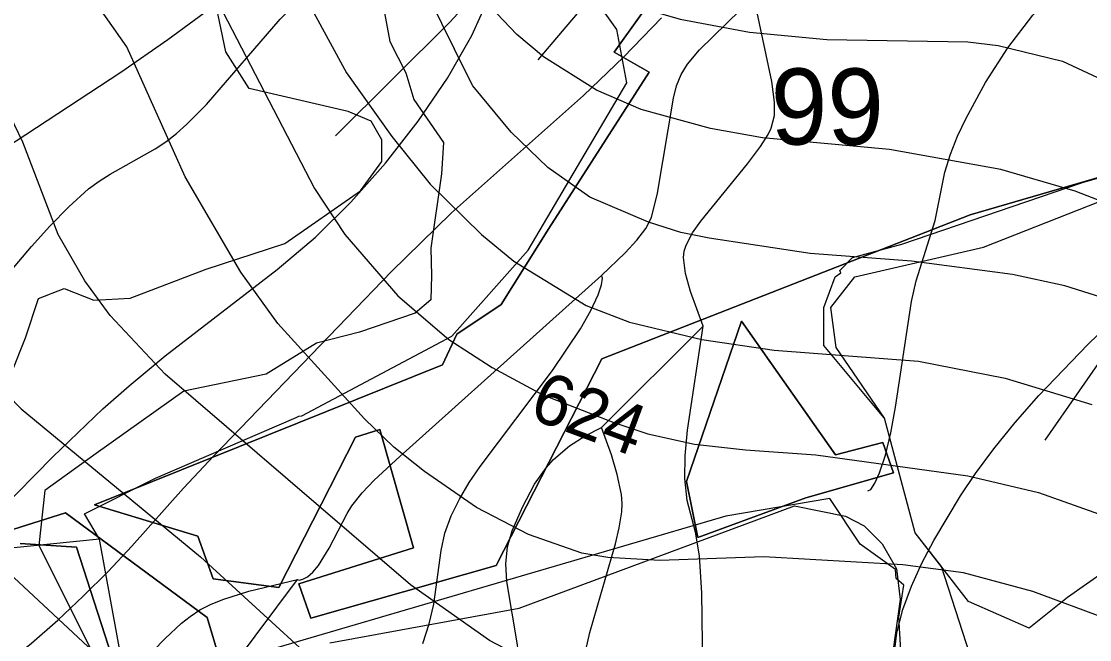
# Model space of a CAD drawing. Extents: x -709584 to -702006, y -1161789 to -1157496.
# Drawn here: x -706146.4 to -705935.7, y -1160043.8 to -1159921.9 of the extents above; entities that cross this region are included whole.
import ezdxf

# ---------------------------------------------------------------- set-up
doc = ezdxf.new("R2010")
doc.units = 0
for name, color, linetype in [('102_obvod PÚ', 7, 'Continuous'), ('120_vrstevnice hlavní', 7, 'Continuous'), ('121_vrstevnice hlavní_popis', 7, 'Continuous'), ('122_vrstevnice základní', 7, 'Continuous'), ('408_BPEJ_linie', 7, 'Continuous'), ('409_BPEJ_popis', 7, 'Continuous'), ('411_akumulovaný odtok', 7, 'Continuous'), ('419_LPIS PB', 7, 'Continuous')]:
    doc.layers.add(name, color=color, linetype=linetype)

msp = doc.modelspace()

# ---------------------------------------------------------------- linework, layer by layer
at = {"layer": '102_obvod PÚ'}
for points in [[(-706132.01, -1160017.23), (-706063.34, -1159989.61), (-706060.53, -1159983.56), (-706051.79, -1159977.72), (-706042.41, -1159962.75), (-706022.6, -1159931.91), (-706029.49, -1159927.99), (-706024.08, -1159920.31), (-706017.53, -1159909.69), (-706010.59, -1159892.53), (-706005.92, -1159884.25), (-705993.15, -1159870.34), (-705985.19, -1159860.82), (-705963.63, -1159831.62), (-705937.51, -1159839.54), (-705930.71, -1159851.23)], [(-705930.71, -1159851.23), (-705937.51, -1159839.54), (-705963.63, -1159831.62), (-705985.19, -1159860.82), (-705993.15, -1159870.34), (-706005.92, -1159884.25), (-706010.59, -1159892.53), (-706017.53, -1159909.69), (-706024.08, -1159920.31), (-706029.49, -1159927.99), (-706022.6, -1159931.91), (-706042.41, -1159962.75), (-706051.79, -1159977.72), (-706060.53, -1159983.56), (-706063.34, -1159989.61), (-706132.01, -1160017.23)], [(-705880.49, -1159937.13), (-705959.3, -1159960.06), (-706031.94, -1159988.44), (-706052.79, -1160029.25), (-706089.31, -1160039.58), (-706091.72, -1160032.86), (-706069.11, -1160025.74), (-706075.72, -1160002.39), (-706080.5, -1160003.91), (-706095.63, -1160033.58), (-706108.58, -1160031.88), (-706111.63, -1160023.46), (-706132.01, -1160017.23)], [(-706132.01, -1160017.23), (-706111.63, -1160023.46), (-706108.58, -1160031.88), (-706095.63, -1160033.58), (-706080.5, -1160003.91), (-706075.72, -1160002.39), (-706069.11, -1160025.74), (-706091.72, -1160032.86), (-706089.31, -1160039.58), (-706052.79, -1160029.25), (-706031.94, -1159988.44), (-705959.3, -1159960.06), (-705880.49, -1159937.13)], [(-706015.27, -1160012.66), (-706004.41, -1159981.02), (-705985.87, -1160007.42), (-705976.51, -1160004.98), (-705974.45, -1160010.97), (-705991.68, -1160015.84), (-706013.02, -1160023.71), (-706015.27, -1160012.66)], [(-706015.27, -1160012.66), (-706013.02, -1160023.71), (-705991.68, -1160015.84), (-705974.45, -1160010.97), (-705976.51, -1160004.98), (-705985.87, -1160007.42), (-706004.41, -1159981.02), (-706015.27, -1160012.66)], [(-706190.18, -1160035.39), (-706137.74, -1160018.82), (-706109.77, -1160039.47), (-706107.33, -1160047.61), (-706126.51, -1160053.66), (-706135.55, -1160025.58), (-706146.66, -1160024.88)], [(-706146.66, -1160024.88), (-706135.55, -1160025.58), (-706126.51, -1160053.66), (-706107.33, -1160047.61), (-706109.77, -1160039.47), (-706137.74, -1160018.82), (-706190.18, -1160035.39)]]:
    msp.add_lwpolyline(points, dxfattribs=at)
at = {"layer": '120_vrstevnice hlavní'}
for points in [[(-706204.73, -1159905.53), (-706198.04, -1159923.77), (-706187.35, -1159946.56), (-706174.67, -1159965.94), (-706157, -1159987.6), (-706146.46, -1159998.29), (-706111.12, -1160027.5), (-706077.49, -1160058.28), (-706072.79, -1160061.84), (-706062.1, -1160068.54), (-706056.26, -1160071.53), (-706050.7, -1160073.88), (-706043.59, -1160076.13), (-706037.31, -1160077.23), (-706030.32, -1160077.38), (-706012.92, -1160072.49), (-705983.77, -1160064.61), (-705952.64, -1160058.71), (-705937.48, -1160056.82)], [(-706066.05, -1159917.09), (-706061.1, -1159927.33)], [(-705852.98, -1160024.04), (-705865.58, -1160016.55), (-705883.13, -1160006.13), (-705903.79, -1159991.45), (-705917.61, -1159982.9), (-705931, -1159977.06), (-705940.62, -1159974.07), (-705950.95, -1159971.79), (-705970.9, -1159969.22), (-705990.85, -1159967.65), (-706010.8, -1159964.66), (-706016.38, -1159963.53), (-706022.77, -1159961.53), (-706034.31, -1159956.54), (-706042.58, -1159950.7), (-706049.84, -1159943.72), (-706057.4, -1159934.6), (-706061.1, -1159927.33)]]:
    msp.add_lwpolyline(points, dxfattribs=at)
at = {"layer": '122_vrstevnice základní'}
for points in [[(-706294.51, -1159822.03), (-706250.48, -1159859.93), (-706244.78, -1159865.49), (-706240.07, -1159871.9), (-706234.94, -1159883.3), (-706227.25, -1159920.35), (-706221.98, -1159937.45), (-706218.7, -1159946), (-706214.57, -1159954.54), (-706206.59, -1159968.79), (-706200.75, -1159977.34), (-706188.96, -1159992.37), (-706182.93, -1159999), (-706109.98, -1160066.97), (-706091.17, -1160085.5), (-706081.56, -1160089.38), (-706061.47, -1160090.96), (-706042.29, -1160091.2)], [(-706041.01, -1159861.21), (-706046.09, -1159868.77), (-706052.66, -1159875.6), (-706056.54, -1159881.16), (-706057.11, -1159885.58), (-706056.97, -1159890.71), (-706055.54, -1159895.84), (-706053.26, -1159900.97), (-706046.99, -1159907.81), (-706041.86, -1159911.51), (-706035.31, -1159914.93), (-706023.34, -1159919.49), (-706016.5, -1159921.49), (-706002.82, -1159924.05), (-705987.57, -1159925.48), (-705959.79, -1159925.9), (-705953.8, -1159926.62), (-705941.12, -1159929.75), (-705928.3, -1159935.74)], [(-705951.3, -1160051.51), (-705957.33, -1160049.33), (-705965.77, -1160047.88), (-705972.24, -1160047.04), (-705979.74, -1160046.88), (-705987.74, -1160047.04), (-705995.7, -1160048.02), (-706013.65, -1160052.3), (-706018.39, -1160053.19), (-706023.62, -1160053.44), (-706031.6, -1160052.87), (-706041.58, -1160050.16), (-706046.69, -1160047.92), (-706054.12, -1160044.03), (-706069.65, -1160033.06), (-706118.1, -1159991.45), (-706128.93, -1159979.91), (-706133.92, -1159973.07), (-706139.19, -1159963.95), (-706146.17, -1159945.71), (-706149.45, -1159938.87), (-706159.57, -1159925.19), (-706172.96, -1159910.23)], [(-705932.43, -1160039.76), (-705946.96, -1160034.34), (-705960.64, -1160030.64), (-705972.61, -1160029.07), (-705999.97, -1160027.5), (-706020.49, -1160028.21), (-706030.75, -1160027.64), (-706035.88, -1160026.79), (-706046.42, -1160023.08), (-706056.68, -1160017.81), (-706066.94, -1160010.69), (-706073, -1160005.91), (-706078.77, -1160000.28), (-706095.87, -1159981.48), (-706103.14, -1159971.36), (-706114.11, -1159952.55), (-706125.65, -1159926.9), (-706132.78, -1159916.64)], [(-705836.19, -1160013.74), (-705859.76, -1159996.01), (-705875.72, -1159985.75), (-705899.94, -1159972.36), (-705924.16, -1159960.96), (-705938.56, -1159955.4), (-705953.23, -1159951.12), (-705975.18, -1159947.14), (-706000.26, -1159944.86), (-706010.52, -1159943), (-706024.2, -1159939.3), (-706033.03, -1159935.45), (-706043.43, -1159928.9), (-706048.7, -1159924.48), (-706056.54, -1159916.21)], [(-706107.55, -1159918.35), (-706088.6, -1159954.83), (-706082.62, -1159963.95), (-706072.21, -1159976.06), (-706062.1, -1159984.61), (-706053.55, -1159990.17), (-706043.57, -1159995.58), (-706029.61, -1160001), (-706022.85, -1160003.28), (-706013.65, -1160005.27), (-706003.58, -1160006.41), (-705989.71, -1160007.41), (-705959.79, -1160011.54), (-705945.82, -1160014.82), (-705927.87, -1160021.23)], [(-706089.17, -1159919.49), (-706082.33, -1159932.03), (-706073.35, -1159944.57), (-706065.8, -1159953.98), (-706055.69, -1159963.95), (-706049.27, -1159969.22), (-706035.03, -1159977.91), (-706026.48, -1159981.19), (-706012.23, -1159984.61), (-705997.98, -1159986.75), (-705969.48, -1159988.89), (-705952.38, -1159992.3), (-705935.28, -1159997.44)]]:
    msp.add_lwpolyline(points, dxfattribs=at)
at = {"layer": '408_BPEJ_linie'}
for points in [[(-706131, -1160024), (-706134, -1160019), (-706120, -1160012), (-706092.24, -1160000), (-706091.72, -1159999.78), (-706091.13, -1159999.73), (-706061.5, -1159984), (-706046.5, -1159967), (-706027, -1159934), (-706029, -1159923.5), (-706049, -1159895.5), (-706058.5, -1159874.5), (-706051.5, -1159868), (-706033.5, -1159863), (-706024, -1159886.5), (-706011.5, -1159889.5), (-705997, -1159877), (-705967.43, -1159835.34), (-705965.3, -1159834.4), (-705962.63, -1159831.21)], [(-705958, -1160051), (-705964.98, -1160029.43), (-705970.16, -1160022.75), (-705976.17, -1160000.15), (-705976.3, -1160000), (-705988.18, -1159985.84), (-705988.18, -1159978.31), (-705985.93, -1159972.28), (-705984.82, -1159971.49), (-705985, -1159971), (-705982.5, -1159968.5), (-705972.8, -1159965.83), (-705937.13, -1159953.68), (-705884.58, -1159938.61), (-705879.05, -1159936.81), (-705879.5, -1159931), (-705888, -1159919), (-705935, -1159863.5), (-705936, -1159850), (-705940, -1159843), (-705962.63, -1159831.21)], [(-705958, -1160051), (-705972.5, -1160053.5), (-705973.4, -1160039.44), (-705972.4, -1160033.1), (-705973.89, -1160031.78), (-705974, -1160030), (-705981, -1160025), (-705987, -1160016), (-706007.5, -1160019.5), (-706108.4, -1160049.1), (-706121.95, -1160050.59), (-706125.16, -1160049.51), (-706126.42, -1160049.2), (-706131, -1160024)], [(-706131, -1160024), (-706150.5, -1160026), (-706193, -1160042), (-706290.5, -1160101), (-706319.5, -1160119.5), (-706347, -1160131), (-706404.5, -1160146), (-706459, -1160146), (-706481.5, -1160149.5), (-706501, -1160161.5), (-706523.5, -1160182), (-706546, -1160220), (-706564.5, -1160251.5), (-706640, -1160329)]]:
    msp.add_lwpolyline(points, dxfattribs=at)
at = {"layer": '411_akumulovaný odtok'}
for p, q in [((-705944.49, -1160004.5), (-705921.99, -1159972)), ((-706031.99, -1160002), (-706011.99, -1159982)), ((-706106.99, -1160052), (-706091.99, -1160032))]:
    msp.add_line(p, q, dxfattribs=at)
for points in [[(-706044.49, -1159929.5), (-706024.2, -1159905.45), (-706016.79, -1159897.19), (-706008.45, -1159889.47), (-705976.99, -1159862)], [(-706161.99, -1159987), (-706144.45, -1159966.3), (-706140.82, -1159962.28), (-706137.1, -1159958.45), (-706133.16, -1159954.94), (-706131.06, -1159953.38), (-706128.92, -1159952.01), (-706120.04, -1159947.04), (-706117.93, -1159945.64), (-706115.81, -1159943.99), (-706113.79, -1159942.19), (-706109.95, -1159938.29), (-706095.39, -1159921.49), (-706089.62, -1159915.47), (-706081.12, -1159907.87), (-706061.99, -1159892)], [(-706284.73, -1160082.36), (-706273.96, -1160068.38), (-706268.75, -1160062.01), (-706246.59, -1160037.13), (-706241.22, -1160030.79), (-706236.12, -1160024.29), (-706224.77, -1160008.22), (-706220.15, -1160002.16), (-706215.29, -1159996.34), (-706210.16, -1159990.79), (-706204.74, -1159985.61), (-706199.69, -1159981.4), (-706194.08, -1159977.32), (-706166.25, -1159957.75), (-706126.83, -1159931.94), (-706117.57, -1159925.5), (-706086.36, -1159902.54), (-706081.34, -1159899.16), (-706078.22, -1159897.38), (-706076.99, -1159897)], [(-706084.49, -1159944.5), (-706061.92, -1159922.04), (-706059.53, -1159919.48), (-706058.12, -1159917.67), (-706056.99, -1159915.73), (-706055.82, -1159912.59), (-706054.63, -1159908.18), (-706051.99, -1159897)], [(-705979.49, -1160014.5), (-705978.92, -1160014.2), (-705978.1, -1160012.99), (-705977.15, -1160010.96), (-705976, -1160007.45), (-705974.96, -1160003.05), (-705974.03, -1159998.01), (-705970.85, -1159977.12), (-705969.93, -1159973.07), (-705966.21, -1159961.17), (-705964.3, -1159951.66), (-705963.2, -1159948.09), (-705961.78, -1159944.52), (-705960.11, -1159940.97), (-705956.26, -1159933.93), (-705951.85, -1159927.1), (-705946.91, -1159920.64), (-705944.25, -1159917.6), (-705941.46, -1159914.75), (-705938.5, -1159912.13), (-705935.33, -1159909.82)], [(-706150.89, -1160018.59), (-706140.23, -1160007.8), (-706130.34, -1159998.33), (-706125.18, -1159993.77), (-706118.05, -1159987.89), (-706095.99, -1159970.83), (-706088.45, -1159964.45), (-706081.46, -1159957.55), (-706074.59, -1159949.83), (-706068.14, -1159941.58), (-706062.38, -1159933.1), (-706057.58, -1159924.68), (-706053.78, -1159916.2)], [(-706031.99, -1159972), (-706027.35, -1159967.54), (-706025.05, -1159965.08), (-706023.25, -1159962.74), (-706022.18, -1159960.55), (-706020.94, -1159955.76), (-706017.81, -1159937.01), (-706017.19, -1159934.61), (-706016.32, -1159932.35), (-706015.06, -1159930.32), (-706012.71, -1159927.53), (-706001.99, -1159917)], [(-706011.99, -1159982), (-706014.47, -1159975.17), (-706015.46, -1159971.6), (-706015.84, -1159968.5), (-706015.69, -1159967.24), (-706015.31, -1159966.01), (-706014.06, -1159963.63), (-706012.45, -1159961.33), (-706003.24, -1159949.99), (-706000.63, -1159946.55), (-705999.15, -1159944.2), (-705998.56, -1159942.98), (-705997.9, -1159940.46), (-705997.86, -1159937.83), (-705998.39, -1159933.74), (-706001.99, -1159917)], [(-706161.41, -1160058.28), (-706144.42, -1160044.53), (-706139.24, -1160039.97), (-706134.21, -1160035.25), (-706129.33, -1160030.39), (-706124.63, -1160025.39), (-706114.46, -1160013.96), (-706108.47, -1160007.57), (-706073.52, -1159971.29), (-706061.61, -1159959.66), (-706035.54, -1159936.52), (-706027.66, -1159928.93), (-706020.16, -1159921.22)], [(-706091.99, -1160032), (-706091.61, -1160032.1), (-706090.9, -1160031.93), (-706089.98, -1160031.43), (-706088.92, -1160030.51), (-706087.83, -1160029.2), (-706085.7, -1160025.82), (-706082.17, -1160018.93), (-706081.28, -1160017.48), (-706079.2, -1160014.86), (-706076.84, -1160012.41), (-706071.81, -1160007.73), (-706031.99, -1159972)], [(-706067.23, -1160044.61), (-706066.02, -1160040.73), (-706065.1, -1160036.84), (-706063.63, -1160026.25), (-706062.88, -1160022.84), (-706061.66, -1160019.42), (-706060.03, -1160016.11), (-706058.1, -1160012.86), (-706055.94, -1160009.67), (-706041.68, -1159990.73), (-706036.18, -1159982.52), (-706034.12, -1159978.9), (-706032.69, -1159975.84), (-706032.03, -1159973.88), (-706031.81, -1159972.56), (-706031.99, -1159972)], [(-705974.31, -1160046.93), (-705973.74, -1160042.48), (-705972.55, -1160037.87), (-705970.88, -1160033.31), (-705968.83, -1160028.79), (-705966.49, -1160024.31), (-705961.21, -1160015.47), (-705958.25, -1160011.06), (-705954.64, -1160006.19), (-705950.43, -1160001.02), (-705945.75, -1159995.72), (-705936.07, -1159985.65), (-705921.99, -1159972)], [(-705996.99, -1160097), (-705997.63, -1160095.69), (-705998.51, -1160092.47), (-705998.86, -1160090.4), (-705999.6, -1160083.1), (-706000.27, -1160080.54), (-706001.23, -1160078.17), (-706002.33, -1160076.09), (-706007.35, -1160067.99), (-706009.56, -1160063.74), (-706010.41, -1160061.52), (-706011.02, -1160059.22), (-706011.43, -1160056.85), (-706012, -1160049.52), (-706012.25, -1160034.59), (-706012.7, -1160027.29), (-706013.47, -1160022.64), (-706015.13, -1160016.39), (-706015.58, -1160012.07), (-706015.5, -1160007.58), (-706015.02, -1160002.5), (-706011.99, -1159982)], [(-706051.99, -1160082), (-706052.88, -1160081.15), (-706053.5, -1160080.11), (-706054.04, -1160078.73), (-706054.36, -1160077.03), (-706054.41, -1160075.1), (-706054.24, -1160073.05), (-706053.36, -1160068.93), (-706049.13, -1160057), (-706048.32, -1160053.61), (-706048.06, -1160050.15), (-706048.57, -1160044.84), (-706050.7, -1160032.37), (-706050.91, -1160028.86), (-706050.54, -1160025.52), (-706049.6, -1160022.36), (-706047.62, -1160017.71), (-706045.24, -1160013.18), (-706042.94, -1160009.95), (-706041.49, -1160008.33), (-706038.32, -1160005.59), (-706035.26, -1160003.63), (-706031.99, -1160002)], [(-706036.99, -1160082), (-706035.12, -1160076.6), (-706034.02, -1160072.72), (-706033.29, -1160068.82), (-706033.19, -1160067.06), (-706033.55, -1160064.01), (-706035.35, -1160056.5), (-706035.86, -1160053.49), (-706035.96, -1160051.98), (-706035.73, -1160048.82), (-706034.32, -1160042.46), (-706029.27, -1160024.96), (-706028.51, -1160021.78), (-706028, -1160018.61), (-706027.93, -1160016.98), (-706028.09, -1160015.21), (-706028.9, -1160011.29), (-706030.07, -1160007.41), (-706031.99, -1160002)], [(-706174.49, -1160104.5), (-706122.71, -1160048.44), (-706118.07, -1160043.62), (-706114.85, -1160040.62), (-706113.16, -1160039.25), (-706111.24, -1160037.98), (-706109.11, -1160036.91), (-706106.71, -1160035.94), (-706101.6, -1160034.31), (-706091.99, -1160032)]]:
    msp.add_lwpolyline(points, dxfattribs=at)
at = {"layer": '419_LPIS PB'}
for points in [[(-706077.44, -1159906.03), (-706073.74, -1159925.86), (-706070.59, -1159932.02), (-706069.01, -1159937.32), (-706063.2, -1159945.79), (-706063.55, -1159951.97), (-706065.67, -1159966.61), (-706065.55, -1159972.03), (-706065.66, -1159976.84), (-706068.73, -1159979.43), (-706079.77, -1159983.22), (-706088.25, -1159985.38), (-706098.15, -1159991.49), (-706114.37, -1159994.81), (-706131.7, -1160007.1), (-706141.81, -1160014.41), (-706142.97, -1160025.26), (-706130.49, -1160050.2)], [(-706148.46, -1159991.43), (-706145.6, -1159984.28), (-706143.07, -1159976.54), (-706138, -1159974.59), (-706132.12, -1159976.91), (-706124.99, -1159976.49), (-706109.98, -1159970.8), (-706094.48, -1159965.68), (-706079.57, -1159955.31), (-706075.35, -1159949.5), (-706075.35, -1159945.26), (-706077.46, -1159941.55), (-706081.95, -1159939.67), (-706101.47, -1159935.16), (-706106.12, -1159927.93), (-706107.97, -1159919.09)], [(-705932.63, -1160030.28), (-705940.13, -1160035.55), (-705947.64, -1160041.57), (-705959.65, -1160036.3), (-705970.16, -1160022.75), (-705976.17, -1160000.15), (-705985.71, -1159986.19), (-705986.77, -1159978.31), (-705982.05, -1159972.28), (-705956.69, -1159966.4), (-705915.26, -1159950.15)], [(-706085.56, -1160044.46), (-706048.27, -1160037.64), (-705993.96, -1160017.44), (-705983.89, -1160019.49), (-705980.18, -1160021.41), (-705976.65, -1160024.94), (-705973.83, -1160029.88), (-705973.11, -1160035.92), (-705975.5, -1160052.8)]]:
    msp.add_lwpolyline(points, dxfattribs=at)

# ---------------------------------------------------------------- texts
at = {"layer": '121_vrstevnice hlavní_popis'}
msp.add_text('624', height=10, rotation=339.6504, dxfattribs=at).set_placement((-706046.64, -1160000.02))
at = {"layer": '409_BPEJ_popis'}
msp.add_text('99', height=15, dxfattribs=at).set_placement((-705998.64, -1159946.19))

doc.saveas('drawing.dxf')
